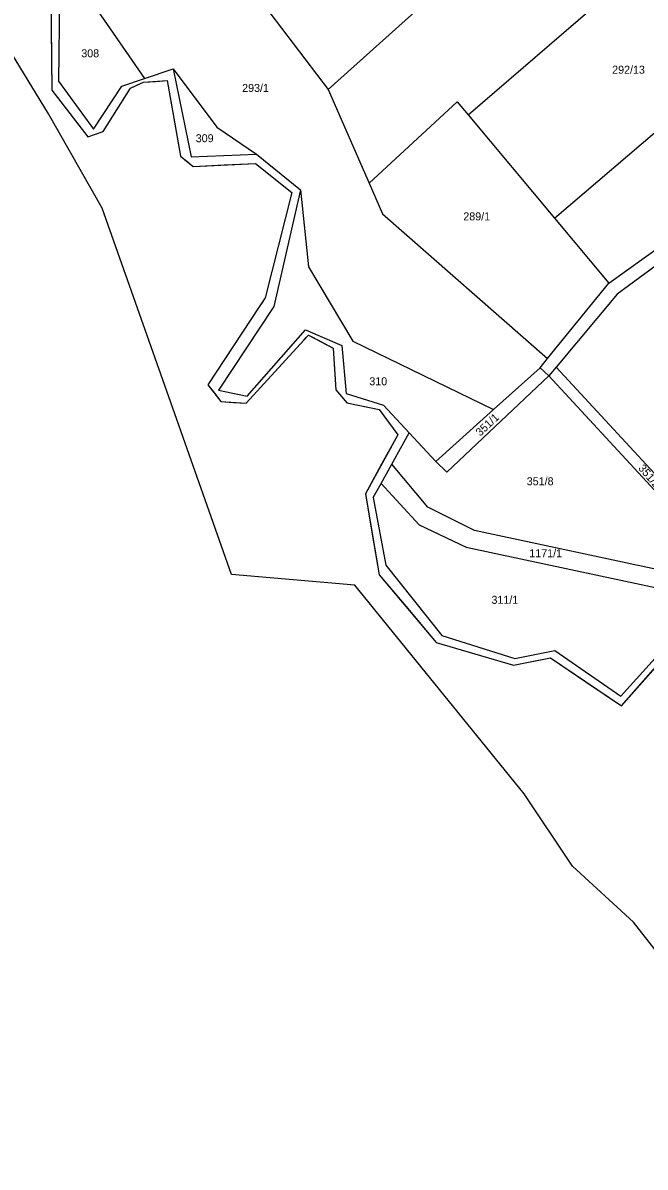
# Model space of a CAD drawing. Extents: x -593358 to -590116, y -1072518 to -1068420.
# Drawn here: x -592628.6 to -592496.4, y -1071584.9 to -1071341.9 of the extents above; entities that cross this region are included whole.
import ezdxf

# ---------------------------------------------------------------- set-up
doc = ezdxf.new("R2010")
doc.units = 0
for name, color, linetype in [('katastrální hranice', 7, 'Continuous'), ('Obvod s Petrovicemi', 7, 'Continuous'), ('Parcela KN', 7, 'Continuous'), ('Parcela ZE', 7, 'Continuous'), ('Parcelní číslo', 7, 'Continuous'), ('vnější obvod_šetřený', 7, 'Continuous')]:
    doc.layers.add(name, color=color, linetype=linetype)

msp = doc.modelspace()

# ---------------------------------------------------------------- linework, layer by layer
at = {"layer": 'katastrální hranice'}
for p, q in [((-592622.76, -1071328.94), (-592622.5, -1071356.12)), ((-592605.79, -1071355.76), (-592603.02, -1071354.45)), ((-592603.02, -1071354.45), (-592597.97, -1071354.11)), ((-592597.97, -1071354.11), (-592595.12, -1071370.16)), ((-592622.5, -1071356.12), (-592614.86, -1071366.04)), ((-592611.56, -1071364.94), (-592605.79, -1071355.76)), ((-592614.86, -1071366.04), (-592611.56, -1071364.94)), ((-592595.12, -1071370.16), (-592592.49, -1071372.37)), ((-592592.49, -1071372.37), (-592579.19, -1071371.7)), ((-592579.19, -1071371.7), (-592571.52, -1071377.88)), ((-592571.52, -1071377.88), (-592577.18, -1071400.29)), ((-592577.18, -1071400.29), (-592578.42, -1071402.18)), ((-592578.42, -1071402.18), (-592589.31, -1071418.7)), ((-592568.94, -1071409.25), (-592567.93, -1071408.15)), ((-592567.93, -1071408.15), (-592562.73, -1071410.95)), ((-592581.23, -1071422.64), (-592568.94, -1071409.25)), ((-592562.73, -1071410.95), (-592562.11, -1071419.82)), ((-592589.31, -1071418.7), (-592586.58, -1071422.29)), ((-592562.11, -1071419.82), (-592559.78, -1071422.53)), ((-592586.58, -1071422.29), (-592581.23, -1071422.64)), ((-592559.78, -1071422.53), (-592552.92, -1071423.97)), ((-592552.92, -1071423.97), (-592548.98, -1071429.33)), ((-592548.98, -1071429.33), (-592555.85, -1071441.87)), ((-592555.85, -1071441.87), (-592552.93, -1071459.07)), ((-592552.93, -1071459.07), (-592540.82, -1071473.44)), ((-592501.48, -1071486.92), (-592486.77, -1071470.26)), ((-592540.82, -1071473.44), (-592524.39, -1071478.3)), ((-592524.39, -1071478.3), (-592516.55, -1071476.74)), ((-592516.55, -1071476.74), (-592501.48, -1071486.92))]:
    msp.add_line(p, q, dxfattribs=at)
at = {"layer": 'Obvod s Petrovicemi'}
for p, q in [((-592511.83, -1071520.92), (-592522.15, -1071505.61)), ((-592498.9, -1071532.82), (-592511.83, -1071520.92)), ((-592458.415, -1071584.865), (-592498.9, -1071532.82))]:
    msp.add_line(p, q, dxfattribs=at)
msp.add_lwpolyline([(-592522.15, -1071505.61), (-592558.14, -1071461.25), (-592584.29, -1071458.98), (-592598.025, -1071420.11), (-592611.76, -1071381.24), (-592623.21, -1071361.17), (-592662.33, -1071297.04), (-592671.15, -1071288.43), (-592694.94, -1071262.33), (-592709.62, -1071235.525), (-592724.3, -1071208.72), (-592769.58, -1071146.52), (-592779.36, -1071128.32), (-592780.91, -1071125.35), (-592801.03, -1071093.6), (-592826.77, -1071049.24), (-592843, -1071006.02), (-592853.91, -1070977.89), (-592844.7, -1070955.31), (-592840.46, -1070953.51), (-592838.86, -1070953.6)], dxfattribs=at)
at = {"layer": 'Parcela KN'}
for p, q in [((-592620.77, -1071327.65), (-592621.09, -1071354.21)), ((-592602.82, -1071353.65), (-592596.7, -1071351.59)), ((-592596.7, -1071351.59), (-592592.9, -1071370.3)), ((-592621.09, -1071354.21), (-592613.66, -1071364.44)), ((-592613.66, -1071364.44), (-592607.62, -1071355.27)), ((-592607.62, -1071355.27), (-592602.82, -1071353.65)), ((-592592.9, -1071370.3), (-592579.02, -1071369.76)), ((-592579.02, -1071369.76), (-592569.68, -1071377.34)), ((-592569.68, -1071377.34), (-592575.35, -1071402.09)), ((-592504.16, -1071397.12), (-592492.89, -1071389.1)), ((-592491.65, -1071391.61), (-592502.36, -1071399.46)), ((-592517.14, -1071413.17), (-592504.16, -1071397.12)), ((-592502.36, -1071399.46), (-592515.3, -1071414.97)), ((-592575.35, -1071402.09), (-592587.11, -1071419.87)), ((-592580.96, -1071421.14), (-592568.59, -1071407.02)), ((-592568.59, -1071407.02), (-592560.89, -1071410.39)), ((-592560.89, -1071410.39), (-592559.92, -1071420.54)), ((-592518.74, -1071415.14), (-592517.14, -1071413.17)), ((-592528.61, -1071423.99), (-592518.74, -1071415.14)), ((-592516.86, -1071416.84), (-592518.74, -1071415.14)), ((-592515.3, -1071414.97), (-592516.86, -1071416.84)), ((-592587.11, -1071419.87), (-592580.96, -1071421.14)), ((-592559.92, -1071420.54), (-592552.02, -1071423.02)), ((-592552.02, -1071423.02), (-592546.54, -1071428.93)), ((-592540.9, -1071435.02), (-592528.61, -1071423.99)), ((-592550.24, -1071435.57), (-592546.54, -1071428.93)), ((-592546.54, -1071428.93), (-592540.9, -1071435.02)), ((-592552.53, -1071439.68), (-592550.24, -1071435.57)), ((-592542.6, -1071444.71), (-592550.24, -1071435.57)), ((-592554.21, -1071442.69), (-592552.53, -1071439.68)), ((-592552.53, -1071439.68), (-592544.47, -1071448.46)), ((-592554.21, -1071442.69), (-592551.51, -1071457.02)), ((-592532.66, -1071449.67), (-592542.6, -1071444.71)), ((-592544.47, -1071448.46), (-592534.44, -1071453.24)), ((-592484.63, -1071459.91), (-592532.66, -1071449.67)), ((-592534.44, -1071453.24), (-592484.51, -1071463.9)), ((-592551.51, -1071457.02), (-592539.64, -1071471.98)), ((-592501.56, -1071484.85), (-592486.01, -1071467.59)), ((-592539.64, -1071471.98), (-592524.09, -1071476.87)), ((-592524.09, -1071476.87), (-592515.62, -1071475.17)), ((-592515.62, -1071475.17), (-592501.56, -1071484.85))]:
    msp.add_line(p, q, dxfattribs=at)
at = {"layer": 'Parcela ZE'}
for p, q in [((-592497.43, -1071296.55), (-592563.76, -1071355.99)), ((-592620.77, -1071327.65), (-592602.82, -1071353.65)), ((-592534.02, -1071361.37), (-592494.16, -1071327.04)), ((-592578.73, -1071336.33), (-592563.76, -1071355.99)), ((-592515.68, -1071383.33), (-592475.14, -1071348.74)), ((-592596.7, -1071351.59), (-592587.46, -1071364.01)), ((-592563.76, -1071355.99), (-592555.06, -1071375.91)), ((-592555.06, -1071375.91), (-592536.34, -1071358.6)), ((-592536.34, -1071358.6), (-592534.02, -1071361.37)), ((-592534.02, -1071361.37), (-592515.68, -1071383.33)), ((-592587.46, -1071364.01), (-592579.02, -1071369.76)), ((-592555.06, -1071375.91), (-592552.22, -1071382.42)), ((-592569.68, -1071377.34), (-592567.92, -1071393.68)), ((-592552.22, -1071382.42), (-592517.14, -1071413.17)), ((-592515.68, -1071383.33), (-592504.16, -1071397.12)), ((-592567.92, -1071393.68), (-592558.55, -1071409.49)), ((-592558.55, -1071409.49), (-592528.61, -1071423.99)), ((-592515.3, -1071414.97), (-592489.59, -1071442.88)), ((-592538.58, -1071437.31), (-592516.86, -1071416.84)), ((-592516.86, -1071416.84), (-592484.88, -1071451.5)), ((-592540.9, -1071435.02), (-592538.58, -1071437.31))]:
    msp.add_line(p, q, dxfattribs=at)
at = {"layer": 'vnější obvod_šetřený'}
msp.add_lwpolyline([(-592622.76, -1071328.94), (-592622.63, -1071342.53), (-592622.5, -1071356.12), (-592618.68, -1071361.08), (-592614.86, -1071366.04), (-592613.21, -1071365.49), (-592611.56, -1071364.94), (-592608.675, -1071360.35), (-592605.79, -1071355.76), (-592604.405, -1071355.105), (-592603.02, -1071354.45), (-592600.495, -1071354.28), (-592597.97, -1071354.11), (-592596.545, -1071362.135), (-592595.12, -1071370.16), (-592593.805, -1071371.265), (-592592.49, -1071372.37), (-592585.84, -1071372.035), (-592579.19, -1071371.7), (-592575.355, -1071374.79), (-592571.52, -1071377.88), (-592574.35, -1071389.085), (-592577.18, -1071400.29), (-592577.8, -1071401.235), (-592578.42, -1071402.18), (-592583.865, -1071410.44), (-592589.31, -1071418.7), (-592587.945, -1071420.495), (-592586.58, -1071422.29), (-592583.905, -1071422.465), (-592581.23, -1071422.64), (-592575.085, -1071415.945), (-592568.94, -1071409.25), (-592568.435, -1071408.7), (-592567.93, -1071408.15), (-592565.33, -1071409.55), (-592562.73, -1071410.95), (-592562.42, -1071415.385), (-592562.11, -1071419.82), (-592560.945, -1071421.175), (-592559.78, -1071422.53), (-592556.35, -1071423.25), (-592552.92, -1071423.97), (-592550.95, -1071426.65), (-592548.98, -1071429.33), (-592552.415, -1071435.6), (-592555.85, -1071441.87), (-592554.39, -1071450.47), (-592552.93, -1071459.07), (-592546.875, -1071466.255), (-592540.82, -1071473.44), (-592532.605, -1071475.87), (-592524.39, -1071478.3), (-592520.47, -1071477.52), (-592516.55, -1071476.74), (-592509.015, -1071481.83), (-592501.48, -1071486.92), (-592494.125, -1071478.59)], dxfattribs=at)

# ---------------------------------------------------------------- texts
at = {"layer": 'Parcelní číslo'}
for s, p in [('308', (-592616.228, -1071349.17)), ('292/13', (-592503.429, -1071352.66)), ('293/1', (-592582.046, -1071356.53)), ('309', (-592591.908, -1071367.21)), ('289/1', (-592535.056, -1071383.81)), ('310', (-592555.03, -1071418.83)), ('351/8', (-592521.579, -1071440.06)), ('1171/1', (-592521.03, -1071455.34)), ('311/1', (-592529.076, -1071465.24))]:
    msp.add_text(s, height=1.7, dxfattribs=at).set_placement(p)
for s, rotation, p in [('351/1', 43.14372, (-592531.465, -1071429.753)), ('351/20', 310.65772, (-592498.002, -1071436.499))]:
    msp.add_text(s, height=1.7, rotation=rotation, dxfattribs=at).set_placement(p)

doc.saveas('drawing.dxf')
